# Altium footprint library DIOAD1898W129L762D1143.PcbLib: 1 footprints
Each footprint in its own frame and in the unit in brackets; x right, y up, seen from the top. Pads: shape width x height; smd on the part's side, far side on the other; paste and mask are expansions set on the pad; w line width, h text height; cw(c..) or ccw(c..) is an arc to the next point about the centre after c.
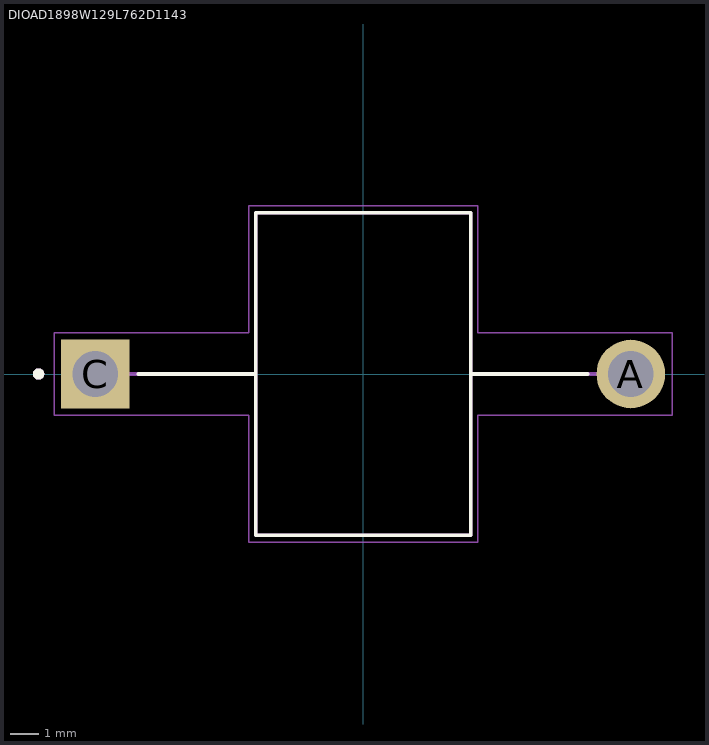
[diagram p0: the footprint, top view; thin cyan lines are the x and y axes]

## DIOAD1898W129L762D1143 [mm]
pads (2):
  round 2.43 hole 1.62: A(9.49,0)
  rect 2.43x2.43 hole 1.62: C(-9.49,0)
Top Overlay:
  circle w0.2: c-11.5,0 r0.1
  lines w0.127: -7.96,0 -3.81,0 ; 7.96,0 3.81,0 ; -3.81,0 -3.81,-5.72 3.81,-5.72 3.81,0 ; -3.81,0 -3.81,5.72 3.81,5.72 3.81,0
Mechanical 13:
  circle w0.2: c-11.5,0 r0.1
  lines w0.127: -8.275,0 -3.81,0 ; 8.275,0 3.81,0 ; -3.81,0 -3.81,-5.72 3.81,-5.72 3.81,0 ; -3.81,0 -3.81,5.72 3.81,5.72 3.81,0
Mechanical 15:
  lines w0.05: -10.955,-1.465 -10.955,1.465 -4.06,1.465 -4.06,5.97 4.06,5.97 4.06,1.465 10.955,1.465 10.955,-1.465 4.06,-1.465 4.06,-5.97 -4.06,-5.97 -4.06,-1.465 -10.955,-1.465
3D body "step_temp.STEP": height 11.5, standoff -6, extent -4.25,-3 4.25,3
